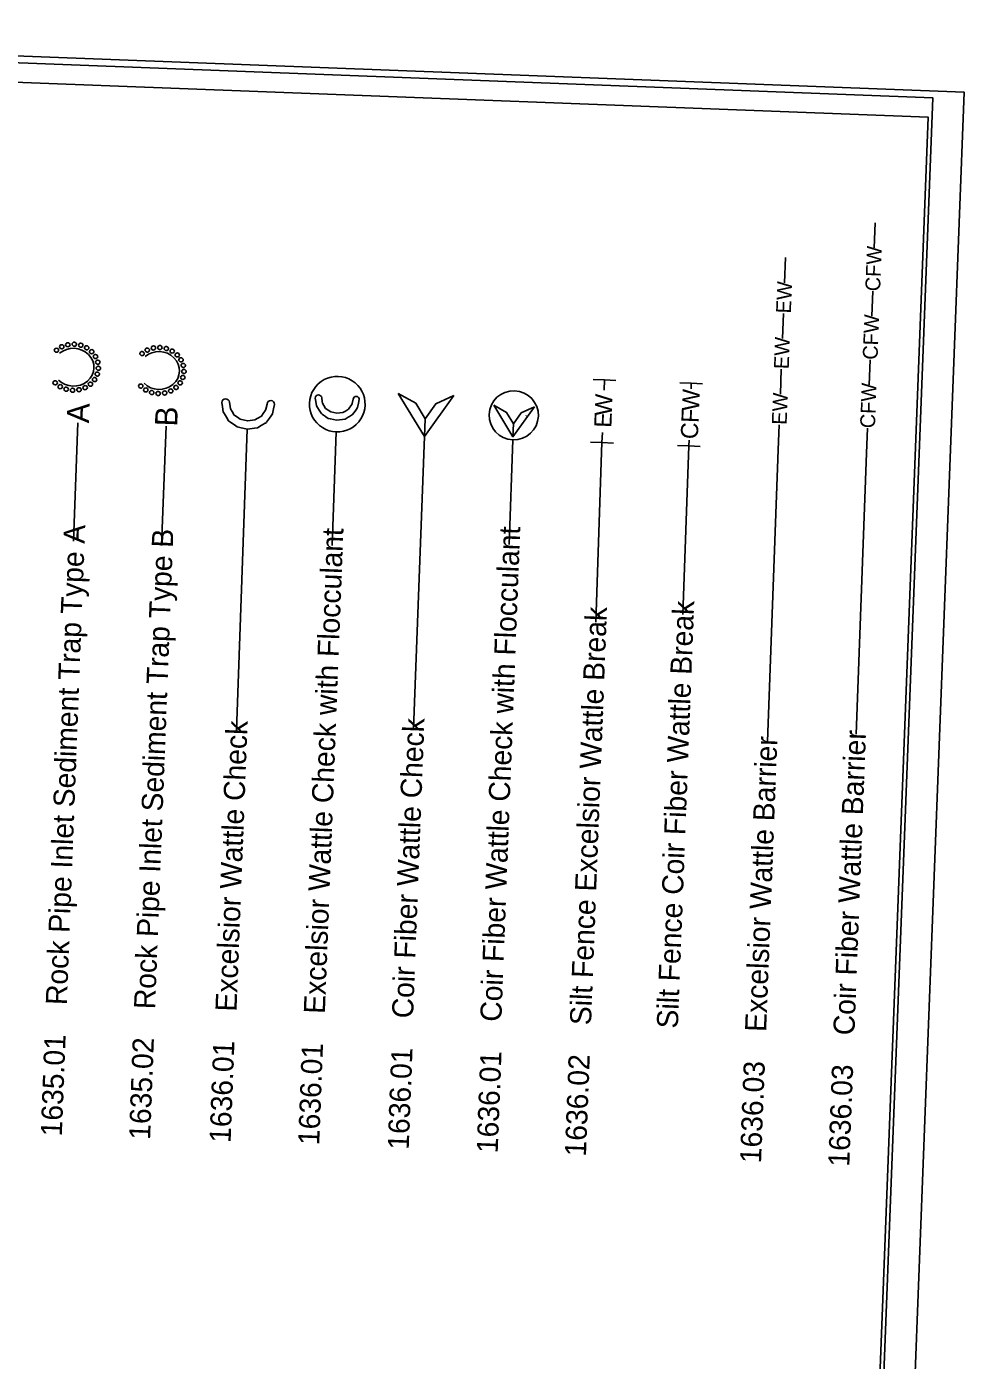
# Model space of a CAD drawing. Extents: x 2094746 to 2100565, y 682095 to 690719.
# Drawn here: x 2097546 to 2100565, y 686425 to 690719 of the extents above; entities that cross this region are included whole.
import ezdxf

# ---------------------------------------------------------------- set-up
doc = ezdxf.new("R2010")
doc.units = 0
for name, color, linetype in [('Exist Road Non-System Type 51 Label', 7, 'Continuous'), ('Exist Road Primary NC Label', 7, 'Continuous'), ('Exist Road Primary NC Shield Number Label', 7, 'Continuous'), ('Exist Road Primary US Label', 7, 'Continuous'), ('Exist Road Primary US Shield CELL', 7, 'Continuous'), ('Exist Road Primary US Shield Number Label', 7, 'Continuous'), ('Exist Road Secondary Type 51 Label', 7, 'Continuous'), ('Sheet Data Field CELL', 7, 'Continuous'), ('Sheet Plot Border Inside CELL', 7, 'Continuous'), ('Sheet Plot Border Outside CELL', 7, 'Continuous'), ('Sheet Title Data Points CELL', 7, 'Continuous')]:
    doc.layers.add(name, color=color, linetype=linetype)

msp = doc.modelspace()

# ---------------------------------------------------------------- linework, layer by layer
at = {"layer": 'Exist Road Non-System Type 51 Label'}
for p, q in [((2099057.4, 689492.5), (2099057.4, 689492.5)), ((2099155.1, 689466.8), (2099154.6, 689464.9))]:
    msp.add_line(p, q, dxfattribs=at)
for points in [[(2099050, 689500.4), (2099111.9, 689398.8), (2099113.5, 689440.2), (2099091.3, 689477.3)], [(2099181.3, 689495.3), (2099111.9, 689398.8), (2099113.5, 689440.2), (2099138.4, 689475.4)]]:
    msp.add_lwpolyline(points, close=True, dxfattribs=at)
msp.add_ellipse((2099114.4, 689467.9), major_axis=(-79.3, 3), ratio=0.995697, dxfattribs=at)
at = {"layer": 'Exist Road Primary NC Label'}
for p, q in [((2100275.4, 690007.3), (2100278.4, 690088)), ((2099986.5, 689894.9), (2099989.5, 689975.5)), ((2100267.1, 689786.9), (2100270.1, 689867.5)), ((2099979.7, 689715.5), (2099982.7, 689796.2)), ((2099973, 689536.2), (2099975.9, 689616.8)), ((2100258.7, 689566.4), (2100261.7, 689647)), ((2099966.2, 689356.8), (2099969.2, 689437.5)), ((2100250.4, 689345.9), (2100253.4, 689426.6))]:
    msp.add_line(p, q, dxfattribs=at)
at = {"layer": 'Exist Road Primary NC Shield Number Label'}
for p, q in [((2098199.2, 689510.2), (2098201.2, 689496)), ((2098201.2, 689496), (2098202.3, 689488.8)), ((2098202.3, 689488.8), (2098207.5, 689480.1)), ((2098207.5, 689480.1), (2098214.5, 689468.7)), ((2098307.9, 689473.3), (2098315.7, 689484.5)), ((2098316.4, 689487.4), (2098315.7, 689484.5)), ((2098316.4, 689487.4), (2098320.3, 689504.1)), ((2098216.3, 689467.5), (2098214.5, 689468.7)), ((2098216.3, 689467.5), (2098224.8, 689461.8)), ((2098233.9, 689455.6), (2098224.8, 689461.8)), ((2098233.9, 689455.6), (2098257.7, 689450.5)), ((2098257.8, 689450.5), (2098257.7, 689450.5)), ((2098257.8, 689450.5), (2098281.1, 689453.5)), ((2098281.1, 689453.5), (2098290.8, 689459)), ((2098290.8, 689459), (2098302.4, 689465.6)), ((2098302.4, 689465.6), (2098307.9, 689473.3))]:
    msp.add_line(p, q, dxfattribs=at)
msp.add_lwpolyline([(2098344.3, 689503.2), (2098341.2, 689489.2), (2098337.7, 689472.8), (2098333.3, 689466.5), (2098328, 689458.9), (2098318.5, 689445.3), (2098318.2, 689445.1), (2098314.7, 689443), (2098314.1, 689442.6), (2098306.5, 689438.1), (2098301.2, 689435), (2098289.6, 689428), (2098280.1, 689426.6), (2098256.8, 689423.1), (2098256.7, 689423.1), (2098232.9, 689428.6), (2098223.6, 689430.7), (2098215.1, 689436.8), (2098213.3, 689438.1), (2098206.1, 689443.3), (2098200.7, 689447.2), (2098199.4, 689448.1), (2098196.6, 689450.1), (2098196.6, 689450.1), (2098189.5, 689462.1), (2098183.1, 689472.7), (2098179.3, 689479.2), (2098176.8, 689495.2), (2098174.6, 689509.3)], dxfattribs=at)
for centre, major_axis, start_param in [((2098187, 689508.8), (-12.3, 0.5), 3.296706), ((2098332.3, 689503.7), (-12, 0.5), 3.141593)]:
    msp.add_ellipse(centre, major_axis=major_axis, ratio=0.995697, start_param=start_param, end_param=6.283185, dxfattribs=at)
at = {"layer": 'Exist Road Primary US Label'}
for p, q in [((2099686, 689571.1), (2099649.2, 689572.5)), ((2099685.3, 689552.8), (2099686, 689571.1)), ((2099686, 689571.1), (2099722.7, 689569.7)), ((2099678.2, 689369.3), (2099641.5, 689370.7)), ((2099678.2, 689369.3), (2099678.9, 689387.6)), ((2099678.2, 689369.3), (2099715, 689367.9))]:
    msp.add_line(p, q, dxfattribs=at)
at = {"layer": 'Exist Road Primary US Shield CELL'}
for p, q in [((2098496.2, 689524.4), (2098497.8, 689512.6)), ((2098497.8, 689512.6), (2098498.7, 689506.6)), ((2098498.7, 689506.6), (2098503.1, 689499.3)), ((2098503.1, 689499.3), (2098508.9, 689489.8)), ((2098510.4, 689488.8), (2098508.9, 689489.8)), ((2098510.4, 689488.8), (2098517.5, 689484)), ((2098525.1, 689478.9), (2098517.5, 689484)), ((2098525.1, 689478.9), (2098545, 689474.6)), ((2098564.5, 689477.1), (2098572.6, 689481.7)), ((2098572.6, 689481.7), (2098582.3, 689487.2)), ((2098582.3, 689487.2), (2098586.8, 689493.6)), ((2098586.8, 689493.6), (2098593.4, 689503)), ((2098593.9, 689505.5), (2098593.4, 689503)), ((2098593.9, 689505.5), (2098597.2, 689519.4)), ((2098545.1, 689474.6), (2098545, 689474.6)), ((2098545.1, 689474.6), (2098564.5, 689477.1))]:
    msp.add_line(p, q, dxfattribs=at)
msp.add_lwpolyline([(2098617.2, 689518.6), (2098614.7, 689506.9), (2098611.7, 689493.3), (2098608.1, 689488), (2098603.6, 689481.6), (2098595.7, 689470.3), (2098595.4, 689470.1), (2098592.5, 689468.4), (2098592, 689468.1), (2098585.7, 689464.3), (2098581.3, 689461.7), (2098571.6, 689455.9), (2098563.6, 689454.7), (2098544.2, 689451.8), (2098544.1, 689451.8), (2098524.3, 689456.3), (2098516.5, 689458.1), (2098509.4, 689463.2), (2098507.9, 689464.3), (2098501.9, 689468.6), (2098497.3, 689471.8), (2098496.3, 689472.6), (2098494, 689474.3), (2098493.9, 689474.3), (2098488, 689484.3), (2098482.7, 689493.2), (2098479.5, 689498.5), (2098477.5, 689511.9), (2098475.6, 689523.6)], dxfattribs=at)
for centre, major_axis, start_param, end_param in [((2098546.3, 689503.8), (89.6, -3.4), 6.283185, 9.424778), ((2098485.9, 689523.2), (-10.3, 0.4), 3.296706, 6.283185), ((2098607.2, 689519), (-10, 0.4), 3.141593, 6.283185), ((2098546.3, 689503.8), (-89.6, 3.4), 6.283185, 9.424778)]:
    msp.add_ellipse(centre, major_axis=major_axis, ratio=0.995697, start_param=start_param, end_param=end_param, dxfattribs=at)
at = {"layer": 'Exist Road Primary US Shield Number Label'}
msp.add_line((2098752.8, 689527.7), (2098752.8, 689527.7), dxfattribs=at)
for points in [[(2098742.8, 689538.5), (2098827.2, 689399.9), (2098829.3, 689456.4), (2098799.1, 689506.9)], [(2098921.9, 689531.6), (2098827.2, 689399.9), (2098829.3, 689456.4), (2098863.4, 689504.5)]]:
    msp.add_lwpolyline(points, close=True, dxfattribs=at)
at = {"layer": 'Exist Road Secondary Type 51 Label'}
for p, q in [((2099406.4, 689581.7), (2099369.7, 689583.1)), ((2099405.1, 689548.8), (2099406.4, 689581.7)), ((2099406.4, 689581.7), (2099443.1, 689580.2)), ((2099398.6, 689380), (2099399.9, 689412.9)), ((2099398.6, 689380), (2099361.9, 689381.4)), ((2099398.6, 689380), (2099435.3, 689378.6))]:
    msp.add_line(p, q, dxfattribs=at)
at = {"layer": 'Sheet Data Field CELL'}
for p, q in [((2097696.7, 689062.4), (2097710.8, 689443.4)), ((2097980.8, 689049), (2097995, 689432.5)), ((2098221.4, 688452.8), (2098256.7, 689423.1)), ((2098530.1, 689048.4), (2098542.9, 689414.5)), ((2098791.9, 688458.2), (2098827.2, 689399.9)), ((2099099.3, 689052), (2099111.4, 689389)), ((2099378.9, 688802.3), (2099398.6, 689380)), ((2099658.8, 688826.5), (2099678.2, 689369.3)), ((2099931.4, 688418), (2099966.2, 689356.8)), ((2100216.8, 688441.1), (2100250.4, 689345.9))]:
    msp.add_line(p, q, dxfattribs=at)
for centre, major_axis in [((2097659.2, 689688.4), (-7.1, 0.27)), ((2097678.9, 689695.1), (-7.1, 0.27)), ((2097699.7, 689696.8), (-7.1, 0.27)), ((2097720.4, 689693.5), (-7.1, 0.27)), ((2097739.5, 689685.3), (-7.1, 0.27)), ((2097975.2, 689686.2), (-7.1, 0.27)), ((2097642.1, 689677.3), (-7.1, 0.27)), ((2097755.6, 689672.9), (-7.1, 0.27)), ((2097767.8, 689657.1), (7.1, -0.27)), ((2097917.6, 689666.7), (-7.1, 0.27)), ((2097934.7, 689677.8), (-7.1, 0.27)), ((2097954.3, 689684.5), (-7.1, 0.27)), ((2097995.9, 689682.9), (-7.1, 0.27)), ((2098014.9, 689674.7), (-7.1, 0.27)), ((2098031.1, 689662.3), (-7.1, 0.27)), ((2098043.3, 689646.5), (7.1, -0.27)), ((2097773.7, 689600.5), (7.1, -0.27)), ((2097775.1, 689638.9), (7.1, -0.27)), ((2097777.1, 689619.6), (7.1, -0.27)), ((2098050.6, 689628.3), (7.1, -0.27)), ((2098052.6, 689609), (7.1, -0.27)), ((2097638.1, 689572.5), (7.1, -0.27)), ((2097654.3, 689560.1), (7.1, -0.27)), ((2097734.5, 689557), (7.1, -0.27)), ((2097751.6, 689568.1), (7.1, -0.27)), ((2097764.9, 689583), (7.1, -0.27)), ((2097913.6, 689561.9), (7.1, -0.27)), ((2098027.1, 689557.5), (7.1, -0.27)), ((2098040.4, 689572.4), (7.1, -0.27)), ((2098049.1, 689589.9), (7.1, -0.27)), ((2097673.3, 689551.9), (7.1, -0.27)), ((2097694, 689548.6), (7.1, -0.27)), ((2097714.9, 689550.3), (7.1, -0.27)), ((2097929.7, 689549.5), (7.1, -0.27)), ((2097948.8, 689541.3), (7.1, -0.27)), ((2097969.5, 689538), (7.1, -0.27)), ((2097990.4, 689539.7), (7.1, -0.27)), ((2098010, 689546.4), (7.1, -0.27))]:
    msp.add_ellipse(centre, major_axis=major_axis, ratio=0.923408, dxfattribs=at)
for centre in [(2097696.9, 689622.7), (2097972.3, 689612.1)]:
    msp.add_ellipse(centre, major_axis=(-65.9, 2.5), ratio=0.923408, start_param=0.785389, end_param=5.497624, dxfattribs=at)
at = {"layer": 'Sheet Plot Border Inside CELL'}
msp.add_lwpolyline([(2100242.3, 682094.5), (2100565.2, 690508.1), (2095069.1, 690719.1), (2094746.1, 682305.5)], close=True, dxfattribs=at)
at = {"layer": 'Sheet Plot Border Outside CELL'}
msp.add_lwpolyline([(2100144.4, 682163.3), (2100464, 690489.5), (2095168.6, 690692.8), (2094849, 682366.6)], close=True, dxfattribs=at)
at = {"layer": 'Sheet Title Data Points CELL'}
msp.add_lwpolyline([(2095178.7, 690629.8), (2094891, 683133.2), (2100161.3, 682931), (2100449, 690427.5)], close=True, dxfattribs=at)

# ---------------------------------------------------------------- texts
at = {"layer": 'Exist Road Primary US Label'}
for s, p in [('W', (2099710.9, 689481.1)), ('F', (2099709.3, 689442.8)), ('C', (2099707.3, 689390.5))]:
    msp.add_text(s, height=55.4, rotation=87.802, dxfattribs=at).set_placement(p)
at = {"layer": 'Exist Road Secondary Type 51 Label'}
for s, p in [('W', (2099430.3, 689465.4)), ('E', (2099428.7, 689427.2))]:
    msp.add_text(s, height=55.4, rotation=87.802, dxfattribs=at).set_placement(p)
at = {"layer": 'Sheet Data Field CELL'}
for s, height, p in [('CFW', 47.77, (2100293.9, 689866.6)), ('EW', 47.77, (2100006.6, 689795.3)), ('CFW', 47.77, (2100285.6, 689646.1)), ('EW', 47.77, (2099999.8, 689615.9)), ('CFW', 47.77, (2100277.2, 689425.6)), ('EW', 47.77, (2099993, 689436.6)), ('A', 71.8, (2097746.6, 689442)), ('B', 71.8, (2098030.8, 689431.1)), ('Rock Pipe Inlet Sediment Trap Type A', 68.045, (2097675.5, 687568.3)), ('Rock Pipe Inlet Sediment Trap Type B', 68.045, (2097959.6, 687554.9)), ('Excelsior Wattle Check with Flocculant', 68.14, (2098506.3, 687540.1)), ('Coir Fiber Wattle Check with Flocculant', 68.14, (2099074.4, 687514.6)), ('Silt Fence Excelsior Wattle Break', 68.167, (2099363.2, 687503.5)), ('Silt Fence Coir Fiber Wattle Break', 68.167, (2099642.8, 687492.8)), ('Coir Fiber Wattle Check', 68.14, (2098790.2, 687525.5)), ('Excelsior Wattle Check', 68.14, (2098221.8, 687547.3)), ('Coir Fiber Wattle Barrier', 68.167, (2100211.2, 687471)), ('Excelsior Wattle Barrier', 68.167, (2099927, 687481.9)), ('1635.01', 68.05, (2097659.3, 687145.5)), ('1635.02', 68.05, (2097943.5, 687134.6)), ('1636.01', 68.05, (2098202.8, 687124.6)), ('1636.01', 68.05, (2098488, 687117.4)), ('1636.01', 68.05, (2098776.2, 687102.6)), ('1636.01', 68.05, (2099062.7, 687091.6)), ('1636.02', 68.05, (2099346.9, 687080.7)), ('1636.03', 68.05, (2099910.6, 687059.1)), ('1636.03', 68.05, (2100194.8, 687048.2))]:
    msp.add_text(s, height=height, rotation=87.802, dxfattribs=at).set_placement(p)

doc.saveas('drawing.dxf')
